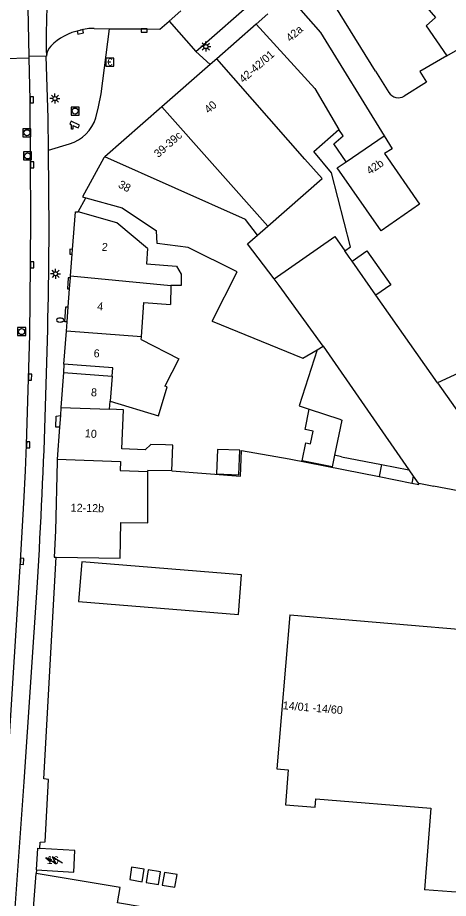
# Model space of a CAD drawing. Extents: x 132998 to 136004, y 396998 to 398512.
# Drawn here: x 133543.5 to 133597.3, y 397305.5 to 397415.5 of the extents above; entities that cross this region are included whole.
import ezdxf

# ---------------------------------------------------------------- set-up
doc = ezdxf.new("R2010")
doc.units = 0
for name, color, linetype in [('gg-afsc-erfafscheiding', 7, 'Continuous'), ('gg-afsc-hekwerk', 7, 'Continuous'), ('gg-anno-huisnummerreeks BGT', 7, 'Continuous'), ('gg-bbg-bijgebouw', 7, 'Continuous'), ('gg-bbg-gedigitaliseerde bebouwing', 7, 'Continuous'), ('gg-bbg-gedigitaliseerde bijgebouw', 7, 'Continuous'), ('gg-bbg-hoofdgebouw', 7, 'Continuous'), ('gg-bbg-luifel en loopbrug', 7, 'Continuous'), ('gg-bbg-tussenscheiding', 7, 'Continuous'), ('gg-knt-verharding', 7, 'Continuous'), ('gg-knt-verharding nz', 7, 'Continuous'), ('gg-kwrk-afval apart plaats', 7, 'Continuous'), ('gt-grn-weggrens', 7, 'Continuous'), ('gt-symb-betaalautomaat', 7, 'Continuous'), ('gt-symb-brandkraan', 7, 'Continuous'), ('gt-symb-camera', 7, 'Continuous'), ('gt-symb-kolk', 7, 'Continuous'), ('gt-symb-lichtmast', 7, 'Continuous'), ('gt-symb-rioolschacht', 7, 'Continuous'), ('gt-symb-trafo symbool', 7, 'Continuous')]:
    doc.layers.add(name, color=color, linetype=linetype)

# ---------------------------------------------------------------- blocks, each defined once
blk = doc.blocks.new('gt0-KOLK')
at = {"layer": 'gt-symb-kolk'}
blk.add_lwpolyline([(0, 0), (0.38, 0), (0.38, 0.4), (-0.37, 0.4), (-0.37, 0), (0, 0)], dxfattribs=at)
blk = doc.blocks.new('gt0-RS')
at = {"layer": 'gt-symb-rioolschacht'}
blk.add_lwpolyline([(-0.5, -0.5), (0.5, -0.5), (0.5, 0.5), (-0.5, 0.5)], close=True, dxfattribs=at)
blk.add_circle((0, 0), 0.375, dxfattribs=at)
blk = doc.blocks.new('gt0-LMAST')
at = {"layer": 'gt-symb-lichtmast'}
for p, q in [((-0.18, 0.17), (-0.45, 0.44)), ((-0.01, 0.25), (-0.01, 0.62)), ((0.17, 0.17), (0.44, 0.44)), ((-0.26, 0), (-0.63, 0)), ((-0.18, -0.18), (-0.45, -0.45)), ((-0.01, -0.25), (-0.01, -0.63)), ((0.44, -0.45), (0.17, -0.18)), ((0.24, 0), (0.62, 0))]:
    blk.add_line(p, q, dxfattribs=at)
blk.add_circle((-0.01, 0), 0.25, dxfattribs=at)
blk = doc.blocks.new('gt0-BA')
at = {"layer": 'gt-symb-betaalautomaat'}
blk.add_lwpolyline([(-0.5, -0.51), (0.5, -0.51), (0.5, 0.49), (-0.5, 0.49)], close=True, dxfattribs=at)
blk.add_text('€', height=0.9, dxfattribs=at).set_placement((-0.36, -0.46))
blk = doc.blocks.new('gt0-CAMERA')
at = {"layer": 'gt-symb-camera'}
for points in [[(0.07, 0.48), (0.75, 0.16), (0.92, 0.51), (-0.12, 1), (-0.28, 0.65), (-0.07, 0.55)], [(0.07, 0.48), (0.07, 0), (-0.07, 0), (-0.07, 0.55)]]:
    blk.add_lwpolyline(points, dxfattribs=at)
blk = doc.blocks.new('gt0-BR')
at = {"layer": 'gt-symb-brandkraan'}
for centre, radius, start, end in [((-0.24, 0), 0.206, 107.5669, 252.4331), ((0.6, -2.66), 3, 106.892, 107.5669), ((0, -0.69), 0.938, 73.108, 106.892), ((-0.6, -2.66), 3, 72.4331, 73.108), ((0.24, 0), 0.206, 287.567, 72.4331), ((0.6, 2.66), 3, 252.4331, 253.108), ((0, 0.69), 0.938, 253.108, 286.8921), ((-0.6, 2.66), 3, 286.8921, 287.567)]:
    blk.add_arc(centre, radius, start, end, dxfattribs=at)
blk = doc.blocks.new('gt0-HSP')
at = {"layer": 'gt-symb-trafo symbool'}
for points in [[(0.77, 0.75), (-0.53, 0), (0.47, 0), (-0.83, -0.75)], [(-0.22, -0.24), (-0.83, -0.75), (-0.08, -0.48)]]:
    blk.add_lwpolyline(points, dxfattribs=at)

msp = doc.modelspace()

# ---------------------------------------------------------------- linework, layer by layer
at = {"layer": 'gg-afsc-erfafscheiding'}
for points in [[(133562.72, 397358.92), (133571.27, 397358.24), (133571.43, 397361.43), (133577.37, 397360.39), (133588.59, 397358.18)], [(133592.7, 397357.37), (133593.55, 397357.21), (133593.58, 397357.35)]]:
    msp.add_lwpolyline(points, dxfattribs=at)
at = {"layer": 'gg-afsc-hekwerk'}
msp.add_lwpolyline([(133546.24, 397311.74), (133546.29, 397312.51), (133546.9, 397312.56), (133547.33, 397320.33), (133546.74, 397320.44), (133548.27, 397348.12)], dxfattribs=at)
at = {"layer": 'gg-bbg-bijgebouw'}
for p, q in [((133583.89, 397360.66), (133588.88, 397359.68)), ((133588.88, 397359.68), (133592.3, 397359.01)), ((133592.3, 397359.01), (133592.87, 397358.22)), ((133593.58, 397357.35), (133595.24, 397357.04)), ((133595.24, 397357.04), (133595.4, 397357.01))]:
    msp.add_line(p, q, dxfattribs=at)
msp.add_lwpolyline([(133592.87, 397358.22), (133593.46, 397357.38), (133593.58, 397357.35)], dxfattribs=at)
at = {"layer": 'gg-bbg-gedigitaliseerde bebouwing'}
for p, q in [((133588.17, 397408.83), (133580.53, 397421.12)), ((133597.04, 397410.74), (133600.19, 397412.56)), ((133588.17, 397408.83), (133589.82, 397406.17)), ((133580.43, 397398.79), (133583.59, 397401.56)), ((133562.61, 397382.07), (133562.55, 397379.69)), ((133558.89, 397375.3), (133558.91, 397375.65)), ((133558.89, 397375.3), (133563.6, 397372.88)), ((133563.6, 397372.88), (133561.86, 397369.5)), ((133549.18, 397371.19), (133555.27, 397370.75)), ((133554.95, 397366.59), (133555.03, 397367.61)), ((133559.71, 397358.83), (133559.71, 397358.96))]:
    msp.add_line(p, q, dxfattribs=at)
for points in [[(133577.27, 397418.22), (133581.29, 397413.65), (133589.25, 397400.75)], [(133597.04, 397410.74), (133593.68, 397408.79), (133594.52, 397407.44), (133591.74, 397405.72)], [(133584.48, 397397.5), (133582.94, 397399.74), (133584.12, 397400.75), (133583.59, 397401.56)], [(133589.25, 397400.75), (133590.24, 397399.14), (133589.27, 397398.54), (133593.64, 397392.21), (133588.87, 397388.89), (133583.36, 397396.74), (133584.48, 397397.5)], [(133584.32, 397386.39), (133585.02, 397386.89), (133582.66, 397396.14), (133580.43, 397398.79)], [(133551.96, 397393.01), (133556.5, 397391.75), (133560.79, 397388.89)], [(133559.69, 397386.67), (133555.84, 397389.89), (133551.03, 397391.24)], [(133567.76, 397377.58), (133570.88, 397383.77), (133564.76, 397386.82), (133560.9, 397387.32), (133560.79, 397388.89)], [(133559.69, 397386.67), (133559.54, 397384.77), (133563.31, 397384.49), (133563.9, 397383.47), (133563.9, 397382.07), (133562.61, 397382.07)], [(133558.91, 397375.65), (133559.23, 397379.93), (133562.55, 397379.69)], [(133567.76, 397377.58), (133579.08, 397372.99), (133580.88, 397374.03)], [(133610.68, 397365.06), (133606.09, 397374.61), (133595.88, 397369.91)], [(133555.27, 397370.75), (133555.34, 397371.77), (133549.23, 397372.25)], [(133555.03, 397367.61), (133561.05, 397365.79), (133562.15, 397369.41), (133561.86, 397369.5)], [(133562.72, 397358.92), (133562.84, 397362.13), (133561.94, 397362.16), (133560.09, 397362.19), (133559.4, 397361.54), (133556.47, 397361.65), (133556.66, 397366.53), (133554.95, 397366.59)], [(133548.27, 397348.12), (133556.27, 397348.01), (133556.33, 397352.45), (133559.71, 397352.41), (133559.71, 397358.83)], [(133577.44, 397340.9), (133613.71, 397337.84), (133614.01, 397341.32), (133614.37, 397341.28), (133614.41, 397341.75), (133625.09, 397340.85), (133624.56, 397334.56), (133625.03, 397334.52), (133624.96, 397333.77), (133624.46, 397333.81), (133624.23, 397331.04), (133625.86, 397330.9)], [(133598.65, 397305), (133598.76, 397306.22), (133594.25, 397306.57)]]:
    msp.add_lwpolyline(points, dxfattribs=at)
msp.add_arc((133591.01, 397406.91), 1.4, 211.8241, 301.844, dxfattribs=at)
at = {"layer": 'gg-bbg-gedigitaliseerde bijgebouw'}
for p, q in [((133595.88, 397369.91), (133588.2, 397380.86)), ((133583.05, 397360.86), (133582.74, 397359.41)), ((133583.89, 397360.66), (133583.05, 397360.86)), ((133598.48, 397356.4), (133595.4, 397357.01))]:
    msp.add_line(p, q, dxfattribs=at)
for points in [[(133585.23, 397385.09), (133584.87, 397385.61), (133584.32, 397386.39)], [(133585.23, 397385.09), (133587.08, 397386.39), (133590.05, 397382.16), (133588.2, 397380.86)], [(133580.88, 397374.03), (133578.61, 397367.01), (133579.87, 397366.59)], [(133582.74, 397359.41), (133579.01, 397360.15), (133579.46, 397362.4), (133580.05, 397362.29), (133580.36, 397363.86), (133579.37, 397364.05), (133579.87, 397366.59)], [(133571.09, 397358.42), (133571.2, 397361.47), (133568.4, 397361.57), (133568.29, 397358.51), (133571.09, 397358.42)]]:
    msp.add_lwpolyline(points, dxfattribs=at)
at = {"layer": 'gg-bbg-hoofdgebouw'}
for p, q in [((133574.71, 397415.98), (133573.24, 397414.68)), ((133573.24, 397414.68), (133568.34, 397410.38)), ((133567.51, 397409.66), (133561.48, 397404.37)), ((133568.34, 397410.38), (133567.51, 397409.66)), ((133561.48, 397404.37), (133554.35, 397398.11)), ((133551.57, 397393.12), (133551.96, 397393.01)), ((133550.32, 397386.57), (133550.68, 397391.25)), ((133550.68, 397391.25), (133551.03, 397391.24)), ((133550.28, 397385.95), (133550.32, 397386.57)), ((133550.07, 397383.27), (133550.28, 397385.95)), ((133549.95, 397381.62), (133550.05, 397383)), ((133550.05, 397383), (133550.07, 397383.27)), ((133549.77, 397379.38), (133549.95, 397381.62)), ((133549.63, 397377.51), (133549.77, 397379.38)), ((133549.54, 397376.35), (133549.63, 397377.51)), ((133549.23, 397372.25), (133549.54, 397376.35)), ((133549.18, 397371.19), (133548.87, 397366.82)), ((133548.87, 397366.82), (133548.79, 397365.82)), ((133548.79, 397365.82), (133548.69, 397364.37)), ((133548.69, 397364.37), (133548.4, 397360.38)), ((133562.72, 397358.92), (133559.71, 397358.96)), ((133545.42, 397304.29), (133545.79, 397308.62))]:
    msp.add_line(p, q, dxfattribs=at)
for points in [[(133554.35, 397398.11), (133554.24, 397398.01), (133551.57, 397393.12)], [(133548.4, 397360.38), (133548.38, 397360.08), (133548.2, 397351.41), (133548, 397348.12), (133548.27, 397348.12)], [(133577.44, 397340.9), (133575.84, 397321.67), (133577.25, 397321.55), (133576.9, 397317.2), (133580.61, 397316.9), (133580.69, 397317.94), (133595.06, 397316.77), (133594.25, 397306.57)], [(133545.81, 397309.05), (133545.97, 397311.76), (133546.24, 397311.74)], [(133545.81, 397309.05), (133550.46, 397308.78), (133550.62, 397311.48), (133546.24, 397311.74)], [(133568.5, 397302.82), (133555.93, 397304.94), (133556.25, 397306.86), (133545.79, 397308.62)]]:
    msp.add_lwpolyline(points, dxfattribs=at)
at = {"layer": 'gg-bbg-luifel en loopbrug'}
for p, q in [((133588.88, 397359.68), (133588.59, 397358.18)), ((133588.59, 397358.18), (133592.7, 397357.37)), ((133592.87, 397358.22), (133592.7, 397357.37))]:
    msp.add_line(p, q, dxfattribs=at)
msp.add_lwpolyline([(133571.02, 397340.95), (133571.43, 397345.9), (133551.46, 397347.55), (133551.05, 397342.6), (133571.02, 397340.95)], dxfattribs=at)
at = {"layer": 'gg-bbg-tussenscheiding'}
for p, q in [((133579.34, 397397.83), (133568.34, 397410.38)), ((133574.72, 397389.48), (133561.48, 397404.37)), ((133584.48, 397397.5), (133589.25, 397400.75)), ((133573.43, 397388.35), (133574.72, 397389.48)), ((133588.2, 397380.86), (133585.23, 397385.09)), ((133550.07, 397383.27), (133562.61, 397382.07)), ((133558.91, 397375.65), (133549.54, 397376.35)), ((133580.88, 397374.03), (133581.61, 397374.46)), ((133581.61, 397374.46), (133592.3, 397359.01)), ((133555.27, 397370.75), (133555.03, 397367.61)), ((133595.88, 397369.91), (133601.7, 397361.62)), ((133548.87, 397366.82), (133554.95, 397366.59))]:
    msp.add_line(p, q, dxfattribs=at)
for points in [[(133586.39, 397426.24), (133594.03, 397417.4), (133595.65, 397415.54), (133594.49, 397414.49), (133597.04, 397410.74)], [(133573.24, 397414.68), (133580.56, 397406.66), (133583.59, 397401.56)], [(133573.43, 397388.35), (133571.9, 397390.31), (133554.35, 397398.11)], [(133574.72, 397389.48), (133581.47, 397395.41), (133579.34, 397397.83)], [(133575.49, 397382.87), (133572.17, 397387.25), (133573.43, 397388.35)], [(133575.49, 397382.87), (133583.06, 397388.19), (133584.32, 397386.39)], [(133581.61, 397374.46), (133576.11, 397382.05), (133575.49, 397382.87)], [(133579.87, 397366.59), (133583.69, 397365.34), (133583.96, 397365.25), (133583.05, 397360.86)], [(133548.4, 397360.38), (133556.31, 397360.08), (133556.27, 397358.96), (133559.71, 397358.83)]]:
    msp.add_lwpolyline(points, dxfattribs=at)
at = {"layer": 'gg-knt-verharding'}
for p, q in [((133562.38, 397415.07), (133563.85, 397416.38)), ((133553.02, 397414.16), (133554.94, 397414.13)), ((133547.33, 397398.95), (133549.93, 397399.77)), ((133547.38, 397388.92), (133547.33, 397398.95)), ((133551.03, 397391.24), (133551.96, 397393.01)), ((133549.23, 397372.25), (133549.18, 397371.19)), ((133548.21, 397364.37), (133548.25, 397365.74)), ((133548.25, 397365.74), (133548.79, 397365.82)), ((133548.69, 397364.37), (133548.21, 397364.37)), ((133545.81, 397309.05), (133545.79, 397308.62))]:
    msp.add_line(p, q, dxfattribs=at)
for points in [[(133554.94, 397414.13), (133559.26, 397414.1), (133561.21, 397414.07), (133562.38, 397415.07)], [(133553.24, 397402.99), (133553.57, 397404.39), (133553.89, 397406), (133554.94, 397414.13)], [(133535.67, 397232.08), (133535.89, 397235.3), (133536.85, 397247.76), (133537.98, 397262.2), (133538.69, 397271.67), (133539.47, 397283.12), (133540.55, 397298.56), (133541.35, 397310.04), (133542.06, 397320.05), (133542.3, 397323.71), (133543.81, 397347.62), (133544.25, 397354.89), (133544.42, 397358.9), (133544.58, 397362.16), (133544.97, 397375.89), (133545.07, 397384.66), (133545.1, 397390.88), (133545.08, 397397.14), (133545.03, 397405.24), (133544.9, 397410.47)], [(133547.33, 397398.95), (133547.27, 397402.95), (133547.04, 397410.72)], [(133550.32, 397386.57), (133549.97, 397386.59), (133549.97, 397385.98), (133550.28, 397385.95)], [(133550.05, 397383), (133549.76, 397383.02), (133549.67, 397381.65), (133549.95, 397381.62)], [(133549.63, 397377.51), (133549.36, 397377.53), (133549.48, 397379.41), (133549.77, 397379.38)], [(133537.85, 397231.91), (133540.17, 397262.14), (133541.26, 397277.13), (133542.78, 397299.08), (133544.27, 397320.04), (133545.93, 397344.96)]]:
    msp.add_lwpolyline(points, dxfattribs=at)
for centre, radius, start, end in [((133628.49, 397412.63), 81.47, 172.0676, 181.3481), ((133552.61, 397407.03), 7.03, 101.1732, 135.3776), ((133552.82, 397408.66), 5.5, 87.8827, 106.6133), ((133549.02, 397410.59), 1.98, 135.7528, 176.3476), ((133548.54, 397404.51), 4.94, 286.3842, 342.1592), ((132706.68, 397394.67), 840.73, 356.61052, 359.60798)]:
    msp.add_arc(centre, radius, start, end, dxfattribs=at)
at = {"layer": 'gg-knt-verharding nz'}
for p, q in [((133565.73, 397411.3), (133574.88, 397419.34)), ((133562.38, 397415.07), (133565.73, 397411.3)), ((133544.9, 397410.47), (133544.9, 397410.66))]:
    msp.add_line(p, q, dxfattribs=at)
msp.add_lwpolyline([(133544.9, 397410.66), (133544.71, 397418.83), (133544.33, 397427.46)], dxfattribs=at)
at = {"layer": 'gg-kwrk-afval apart plaats'}
for points in [[(133557.49, 397307.86), (133559.02, 397307.55), (133559.27, 397309.14), (133557.69, 397309.41), (133557.49, 397307.86)], [(133559.49, 397307.48), (133561.04, 397307.22), (133561.31, 397308.81), (133559.75, 397309.07), (133559.49, 397307.48)], [(133561.52, 397307.16), (133563.08, 397306.89), (133563.36, 397308.48), (133561.8, 397308.74), (133561.52, 397307.16)]]:
    msp.add_lwpolyline(points, dxfattribs=at)
at = {"layer": 'gt-grn-weggrens'}
for p, q in [((133544.9, 397410.47), (133541.79, 397410.38)), ((133547.04, 397410.72), (133544.9, 397410.66)), ((133565.73, 397411.3), (133567.51, 397409.66))]:
    msp.add_line(p, q, dxfattribs=at)

# ---------------------------------------------------------------- block references
at = {"layer": 'gt-symb-betaalautomaat'}
msp.add_blockref('gt0-BA', (133554.99, 397409.98), dxfattribs=at)
at = {"layer": 'gt-symb-brandkraan'}
msp.add_blockref('gt0-BR', (133548.76, 397377.74), dxfattribs=at)
at = {"layer": 'gt-symb-camera'}
msp.add_blockref('gt0-CAMERA', (133550.27, 397401.58), dxfattribs=at)
at = {"layer": 'gt-symb-kolk'}
for p, rotation in [((133551.24, 397413.93), -165.3472126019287), ((133559.26, 397414.1), 179.58037644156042), ((133545.03, 397405.24), -89.65300163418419), ((133545.08, 397397.14), -89.83053410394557), ((133545.07, 397384.66), -90.66169648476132), ((133544.82, 397370.62), -91.64648745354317), ((133544.58, 397362.16), -92.76085565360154), ((133543.81, 397347.62), -93.60955719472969)]:
    msp.add_blockref('gt0-KOLK', p, dxfattribs=dict(at, rotation=rotation))
at = {"layer": 'gt-symb-lichtmast'}
for p in [(133566.97, 397411.9), (133548.12, 397405.4), (133548.2, 397383.52)]:
    msp.add_blockref('gt0-LMAST', p, dxfattribs=at)
at = {"layer": 'gt-symb-rioolschacht'}
for p in [(133550.64, 397403.85), (133544.62, 397401.14), (133544.7, 397398.24), (133543.96, 397376.3)]:
    msp.add_blockref('gt0-RS', p, dxfattribs=at)
at = {"layer": 'gt-symb-trafo symbool', "rotation": -60.71717142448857}
msp.add_blockref('gt0-HSP', (133548.04, 397310.22), dxfattribs=at)

# ---------------------------------------------------------------- texts
at = {"layer": 'gg-anno-huisnummerreeks BGT'}
for s, rotation, p in [('42a', 41.3, (133577.51, 397412.44)), ('42-42/01', 41.3, (133571.65, 397407.3)), ('40', 41.3, (133567.31, 397403.49)), ('39-39c', 41.3, (133561.02, 397397.97)), ('42b', 35, (133587.45, 397395.85)), ('38', 331.4, (133555.93, 397394.38)), ('2', 355.6, (133553.93, 397386.4)), ('4', 355.6, (133553.37, 397378.98)), ('6', 355.6, (133552.92, 397373.11)), ('8', 355.9, (133552.59, 397368.24)), ('10', 355.9, (133551.83, 397363.11)), ('12-12b', 358.8, (133550.08, 397353.81)), ('14/01 -14/60', 355.2, (133576.54, 397329.13)), ('16', 356.6, (133547.08, 397309.83))]:
    msp.add_text(s, height=1, rotation=rotation, dxfattribs=at).set_placement(p)

doc.saveas('drawing.dxf')
